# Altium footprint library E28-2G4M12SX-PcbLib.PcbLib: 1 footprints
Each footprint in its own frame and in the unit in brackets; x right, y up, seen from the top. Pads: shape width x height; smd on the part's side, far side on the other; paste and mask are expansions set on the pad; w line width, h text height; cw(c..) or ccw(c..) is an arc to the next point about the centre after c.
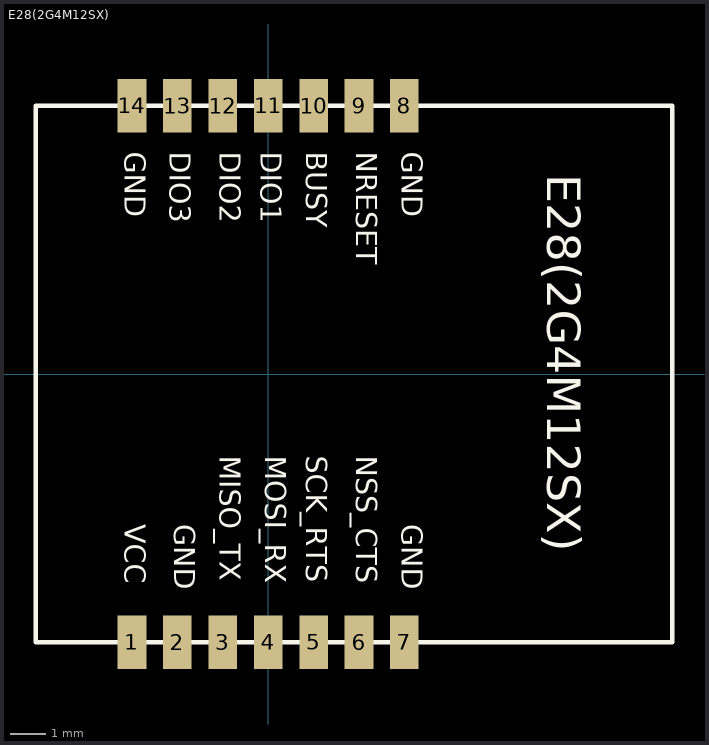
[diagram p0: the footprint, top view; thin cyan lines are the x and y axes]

## E28(2G4M12SX) [mm] "24mm*15mm*2.85mm-S"
pads (14):
  rect 0.8x1.5 smd: 1(-3.81,-7.5) 2(-2.54,-7.5) 3(-1.27,-7.5) 4(0,-7.5) 5(1.27,-7.5) 6(2.54,-7.5) 7(3.81,-7.5) 8(3.81,7.5) 9(2.54,7.5) 10(1.27,7.5) 11(0,7.5) 12(-1.27,7.5) 13(-2.54,7.5) 14(-3.81,7.5)
Top Overlay:
  lines w0.127: -6.5,-7.5 11.3,-7.5 11.3,7.5 -6.5,7.5 -6.5,-7.5
  text "VCC" at -4.214,-4.198 h1
  text "GND" at -2.817,-4.198 h1
  text "MISO_TX" at -1.547,-2.293 h1
  text "MOSI_RX" at -0.277,-2.293 h1
  text "SCK_RTS" at 0.866,-2.293 h1
  text "NSS_CTS" at 2.263,-2.293 h1
  text "GND" at 3.533,-4.198 h1
  text "GND" at 3.533,6.216 h1
  text "NRESET" at 2.263,6.216 h1
  text "BUSY" at 0.866,6.216 h1
  text "DIO1" at -0.404,6.216 h1
  text "DIO2" at -1.547,6.216 h1
  text "DIO3" at -2.944,6.216 h1
  text "GND" at -4.214,6.216 h1
  text "E28(2G4M12SX)" at 7.493,5.588 h1.6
